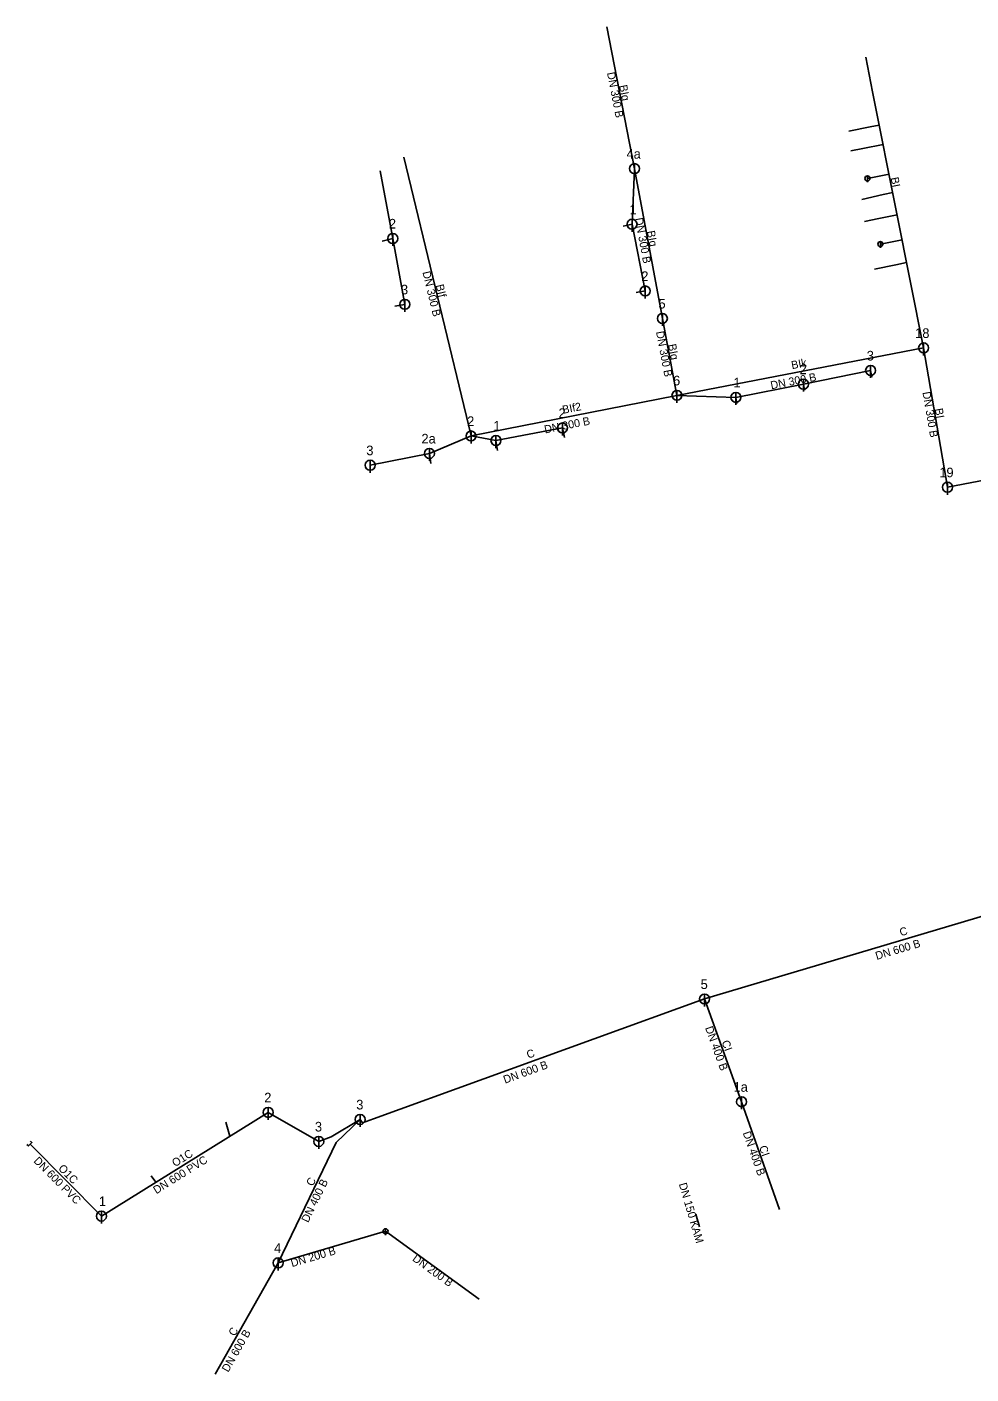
# Model space of a CAD drawing. Extents: x -452579 to -451108, y -1100145 to -1099658.
# Drawn here: x -452579.1 to -452389.8, y -1100145 to -1099874.9 of the extents above; entities that cross this region are included whole.
import ezdxf

# ---------------------------------------------------------------- set-up
doc = ezdxf.new("R2010")
doc.units = 0
for name, color, linetype in [('_odlehcovaci_stoka_smvak_z_dokumentace_', 7, 'Continuous'), ('_pripojka_kanal_destova_prevzato_z_dokumentace_', 7, 'Continuous'), ('_pripojka_kanal_jednotna_prevzato_z_dokumentace_', 7, 'Continuous'), ('_pripojka_kanal_jednotna_priblizne_', 7, 'Continuous'), ('_pripojka_kanal_splaskova_prevzato_z_dokumentace_', 7, 'Continuous'), ('_stoka_jednotna_smvak_prevzato_z_dokumentace_', 7, 'Continuous'), ('Default', 7, 'Continuous'), ('MoLevel 117', 7, 'Continuous'), ('MoLevel 118', 7, 'Continuous'), ('MoLevel 119', 7, 'Continuous'), ('MoLevel 120', 7, 'Continuous'), ('MoLevel 124', 7, 'Continuous'), ('MoLevel 55', 7, 'Continuous'), ('MoLevel 57', 7, 'Continuous'), ('MoLevel 68', 7, 'Continuous'), ('MoLevel 69', 7, 'Continuous')]:
    doc.layers.add(name, color=color, linetype=linetype)

# ---------------------------------------------------------------- blocks, each defined once
blk = doc.blocks.new('_vyust_objekt_')
at = {"layer": 'Default'}
blk.add_lwpolyline([(0.00004, 0.00005), (0, 0.00005), (0, -0.00005), (0.00004, -0.00005), (0.00004, -0.00005)], dxfattribs=at)
blk = doc.blocks.new('_sachta_kanal_prip_')
at = {"layer": 'Default'}
blk.add_line((0, 0.00005), (0, -0.000075), dxfattribs=at)
blk.add_circle((0, 0), 0.00005, dxfattribs=at)
blk = doc.blocks.new('_sachta_kanal_prevzato_z_dokumentace_')
at = {"layer": 'Default'}
blk.add_line((0, 0.00005), (0, -0.000075), dxfattribs=at)
blk.add_circle((0, 0), 0.00005, dxfattribs=at)

msp = doc.modelspace()

# ---------------------------------------------------------------- linework, layer by layer
at = {"layer": '_odlehcovaci_stoka_smvak_z_dokumentace_'}
for p, q in [((-452530.76, -1100092.57), (-452564.2, -1100113.37)), ((-452520.61, -1100098.41), (-452530.76, -1100092.57)), ((-452564.2, -1100113.37), (-452578.5, -1100098.96))]:
    msp.add_line(p, q, dxfattribs=at)
msp.add_lwpolyline([(-452512.33, -1100093.99), (-452518.1, -1100097.49), (-452520.61, -1100098.41)], dxfattribs=at)
at = {"layer": '_pripojka_kanal_destova_prevzato_z_dokumentace_'}
for points in [[(-452414.34, -1099895.82), (-452410.05, -1099894.96), (-452408.22, -1099894.6)], [(-452413.91, -1099899.76), (-452411.49, -1099899.28), (-452407.44, -1099898.47)], [(-452411.7, -1099909.49), (-452407.43, -1099908.54), (-452405.52, -1099908.12)], [(-452411.17, -1099913.92), (-452408.31, -1099913.35), (-452404.62, -1099912.61)], [(-452409.19, -1099923.46), (-452404.9, -1099922.6), (-452402.72, -1099922.16)]]:
    msp.add_lwpolyline(points, dxfattribs=at)
at = {"layer": '_pripojka_kanal_jednotna_prevzato_z_dokumentace_'}
for p, q in [((-452459.56, -1099914.89), (-452457.79, -1099914.47)), ((-452507.89, -1099917.84), (-452505.77, -1099917.34)), ((-452456.93, -1099928.18), (-452455.15, -1099927.86)), ((-452423.21, -1099947.77), (-452423.42, -1099946.55)), ((-452436.76, -1099950.43), (-452436.96, -1099949.2)), ((-452484.75, -1099959.83), (-452485.08, -1099957.85)), ((-452498.16, -1099962.43), (-452498.42, -1099960.44)), ((-452539.26, -1100094.51), (-452538.42, -1100097.34)), ((-452554.2, -1100105.28), (-452553.3, -1100106.59))]:
    msp.add_line(p, q, dxfattribs=at)
at = {"layer": '_pripojka_kanal_jednotna_priblizne_'}
for p, q in [((-452445, -1100112.97), (-452444.25, -1100115.54)), ((-452507.22, -1100116.42), (-452528.75, -1100122.76)), ((-452488.42, -1100130.01), (-452507.22, -1100116.42))]:
    msp.add_line(p, q, dxfattribs=at)
at = {"layer": '_pripojka_kanal_splaskova_prevzato_z_dokumentace_'}
for p, q in [((-452410.59, -1099905.29), (-452406.25, -1099904.43)), ((-452407.99, -1099918.45), (-452403.63, -1099917.58))]:
    msp.add_line(p, q, dxfattribs=at)
at = {"layer": '_stoka_jednotna_smvak_prevzato_z_dokumentace_'}
for p, q in [((-452457.29, -1099903.34), (-452462.82, -1099874.91)), ((-452490.08, -1099956.94), (-452503.54, -1099901.01)), ((-452505.77, -1099917.34), (-452508.28, -1099903.74)), ((-452457.79, -1099914.47), (-452457.29, -1099903.34)), ((-452451.71, -1099933.37), (-452457.29, -1099903.34)), ((-452455.15, -1099927.86), (-452457.79, -1099914.47)), ((-452503.35, -1099930.54), (-452505.77, -1099917.34)), ((-452505.35, -1099930.94), (-452503.35, -1099930.54)), ((-452448.78, -1099948.79), (-452451.71, -1099933.37)), ((-452448.78, -1099948.79), (-452399.31, -1099939.28)), ((-452394.52, -1099967.22), (-452399.31, -1099939.28)), ((-452409.94, -1099943.8), (-452423.42, -1099946.55)), ((-452409.68, -1099945.13), (-452409.94, -1099943.8)), ((-452448.78, -1099948.79), (-452490.08, -1099956.94)), ((-452436.96, -1099949.2), (-452448.78, -1099948.79)), ((-452423.42, -1099946.55), (-452436.96, -1099949.2)), ((-452498.42, -1099960.44), (-452490.08, -1099956.94)), ((-452485.08, -1099957.85), (-452490.08, -1099956.94)), ((-452471.75, -1099955.33), (-452485.08, -1099957.85)), ((-452471.35, -1099957.22), (-452471.75, -1099955.33)), ((-452346.22, -1099957.89), (-452394.52, -1099967.22)), ((-452510.3, -1099962.8), (-452498.42, -1099960.44)), ((-452363.18, -1100045.94), (-452443.25, -1100069.84)), ((-452443.25, -1100069.84), (-452509.66, -1100093.88)), ((-452435.83, -1100090.44), (-452443.25, -1100069.84)), ((-452428.24, -1100112.02), (-452435.83, -1100090.44)), ((-452528.75, -1100122.76), (-452541.37, -1100145.05))]:
    msp.add_line(p, q, dxfattribs=at)
for points in [[(-452399.31, -1099939.28), (-452404.66, -1099912.42), (-452409.55, -1099887.91), (-452410.93, -1099881)], [(-452512.32, -1100093.99), (-452517.09, -1100098.59), (-452528.75, -1100122.76)], [(-452509.66, -1100093.88), (-452511.87, -1100094.68), (-452512.32, -1100093.99)]]:
    msp.add_lwpolyline(points, dxfattribs=at)

# ---------------------------------------------------------------- block references
at = {"layer": 'MoLevel 119', "xscale": 20000, "yscale": 20000}
for p in [(-452457.29, -1099903.33), (-452457.79, -1099914.47), (-452505.77, -1099917.34), (-452455.15, -1099927.86), (-452503.35, -1099930.54), (-452451.71, -1099933.37), (-452399.31, -1099939.28), (-452409.94, -1099943.8), (-452423.42, -1099946.55), (-452448.78, -1099948.79), (-452436.96, -1099949.2), (-452471.75, -1099955.33), (-452490.08, -1099956.94), (-452485.08, -1099957.85), (-452498.42, -1099960.44), (-452510.3, -1099962.8), (-452394.52, -1099967.22), (-452443.25, -1100069.84), (-452435.83, -1100090.44), (-452530.76, -1100092.57), (-452512.32, -1100093.99), (-452520.61, -1100098.41), (-452564.2, -1100113.37), (-452528.75, -1100122.76)]:
    msp.add_blockref('_sachta_kanal_prevzato_z_dokumentace_', p, dxfattribs=at)
at = {"layer": 'MoLevel 55', "xscale": 10000, "yscale": 10000, "rotation": 134.780477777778}
msp.add_blockref('_vyust_objekt_', (-452578.5, -1100098.96), dxfattribs=at)
at = {"layer": 'MoLevel 57', "xscale": 10000, "yscale": 10000}
for p in [(-452410.59, -1099905.29), (-452407.99, -1099918.45), (-452507.22, -1100116.42)]:
    msp.add_blockref('_sachta_kanal_prip_', p, dxfattribs=at)

# ---------------------------------------------------------------- texts
at = {"layer": 'MoLevel 117'}
for rotation, p in [(314.7805, (-452577.93, -1100102.42)), (31.882, (-452553.19, -1100109.01))]:
    msp.add_text('DN 600 PVC', height=1.605, rotation=rotation, dxfattribs=at).set_placement(p)
at = {"layer": 'MoLevel 118'}
for rotation, p in [(31.882, (-452549.43, -1100103.58)), (314.7805, (-452572.97, -1100103.94))]:
    msp.add_text('O1C', height=1.605, rotation=rotation, dxfattribs=at).set_placement(p)
at = {"layer": 'MoLevel 120'}
for s, height, p in [('4a', 1.926, (-452458.89, -1099901.33)), ('1', 1.93, (-452458.29, -1099912.47)), ('2', 1.93, (-452506.55, -1099915.34)), ('2', 1.93, (-452455.93, -1099925.86)), ('3', 1.93, (-452504.13, -1099928.54)), ('5', 1.93, (-452452.49, -1099931.37)), ('18', 1.926, (-452401.01, -1099937.28)), ('3', 1.93, (-452410.72, -1099941.8)), ('2', 1.93, (-452424.2, -1099944.55)), ('6', 1.93, (-452449.56, -1099946.79)), ('1', 1.93, (-452437.46, -1099947.2)), ('2', 1.93, (-452472.53, -1099953.33)), ('2', 1.93, (-452490.86, -1099954.94)), ('1', 1.93, (-452485.59, -1099955.85)), ('2a', 1.926, (-452500.02, -1099958.44)), ('3', 1.93, (-452511.08, -1099960.8)), ('19', 1.926, (-452396.17, -1099965.22)), ('5', 1.93, (-452444.03, -1100067.84)), ('1a', 1.926, (-452437.43, -1100088.44)), ('2', 1.93, (-452531.54, -1100090.57)), ('3', 1.93, (-452513.1, -1100091.99)), ('3', 1.93, (-452521.39, -1100096.41)), ('1', 1.93, (-452564.7, -1100111.37)), ('4', 1.93, (-452529.58, -1100120.76))]:
    msp.add_text(s, height=height, dxfattribs=at).set_placement(p)
at = {"layer": 'MoLevel 124'}
for s, rotation, p in [('DN 150 KAM', 286.2034, (-452448.42, -1100106.94)), ('DN 200 B', 16.4038, (-452525.97, -1100123.61)), ('DN 200 B', 324.1323, (-452501.97, -1100122.2))]:
    msp.add_text(s, height=1.605, rotation=rotation, dxfattribs=at).set_placement(p)
at = {"layer": 'MoLevel 68'}
for s, rotation, p in [('DN 300 B', 281.022, (-452462.82, -1099884.12)), ('DN 300 B', 280.5176, (-452457.22, -1099913.32)), ('DN 300 B', 283.5287, (-452499.83, -1099924.09)), ('DN 300 B', 280.7759, (-452452.99, -1099936.06)), ('DN 300 B', 10.8843, (-452429.86, -1099947.59)), ('DN 300 B', 279.7367, (-452399.55, -1099948.18)), ('DN 300 B', 11.1535, (-452475.23, -1099956.44)), ('DN 600 B', 16.6223, (-452408.72, -1100062.01)), ('DN 400 B', 289.8092, (-452443.16, -1100075.63)), ('DN 600 B', 19.9008, (-452483.26, -1100086.83)), ('DN 400 B', 289.3794, (-452435.61, -1100096.69)), ('DN 400 B', 64.2303, (-452522.74, -1100114.8)), ('DN 600 B', 60.4923, (-452538.77, -1100144.8))]:
    msp.add_text(s, height=1.605, rotation=rotation, dxfattribs=at).set_placement(p)
at = {"layer": 'MoLevel 69'}
for s, height, rotation, p in [('BIg', 1.605, 281.022, (-452460.38, -1099886.68)), ('BI', 1.605, 281.2843, (-452405.94, -1099905.19)), ('BIg', 1.605, 280.5176, (-452454.81, -1099915.9)), ('BIf', 1.605, 283.5287, (-452497.16, -1099926.72)), ('BIg', 1.605, 280.7759, (-452450.56, -1099938.63)), ('BIk', 1.605, 10.8843, (-452425.7, -1099943.55)), ('BIf2', 1.605, 11.1535, (-452471.61, -1099952.49)), ('BI', 1.605, 279.7367, (-452397.07, -1099951.51)), ('C', 1.6, 16.6223, (-452403.87, -1100057.28)), ('CI', 1.605, 289.8092, (-452439.86, -1100078.44)), ('C', 1.6, 19.9008, (-452478.6, -1100081.83)), ('CI', 1.605, 289.3794, (-452432.35, -1100099.53)), ('C', 1.6, 64.2303, (-452521.78, -1100107.51)), ('C', 1.6, 60.4923, (-452537.44, -1100137.59))]:
    msp.add_text(s, height=height, rotation=rotation, dxfattribs=at).set_placement(p)

doc.saveas('drawing.dxf')
